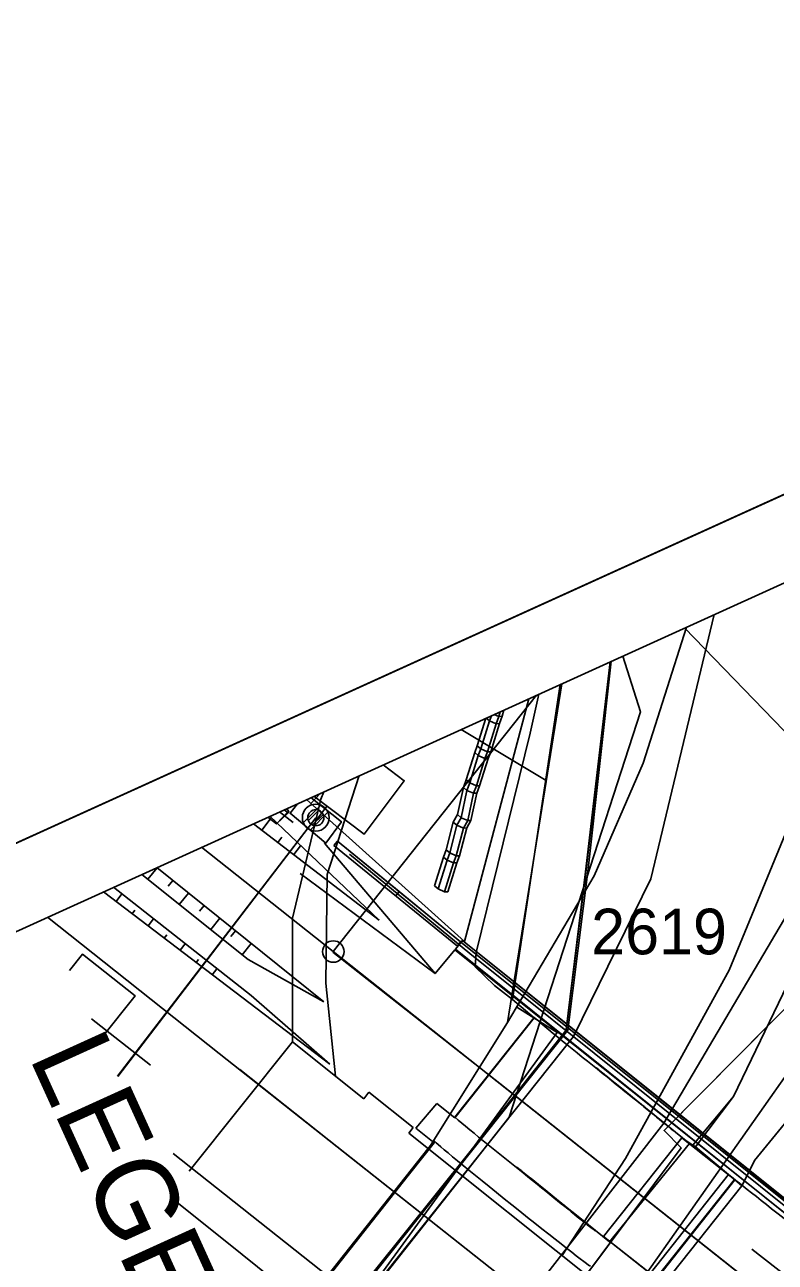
# Model space of a CAD drawing. Extents: x -735603 to -735159, y -1043062 to -1042557.
# Drawn here: x -735536.9 to -735508.95, y -1042665.87 to -1042619.77 of the extents above; entities that cross this region are included whole.
import ezdxf

# ---------------------------------------------------------------- set-up
doc = ezdxf.new("R2010")
doc.units = 0
for name, color, linetype in [('01_ramecek', 7, 'Continuous'), ('02_hranice parcel KN', 7, 'Continuous'), ('03_hranice dráhy', 7, 'Continuous'), ('05_vnitřní kresba', 7, 'Continuous'), ('095_LEGENDA', 7, 'Continuous'), ('CD_6kV', 7, 'Continuous'), ('CD_Telematika', 7, 'Continuous'), ('komunikace_chodníky', 7, 'Continuous'), ('mosty', 7, 'Continuous'), ('nn_ osvetl - ČD', 7, 'Continuous'), ('obvod stavby', 7, 'Continuous'), ('obvod_staveniste', 7, 'Continuous'), ('ploty_zdi_zábradlí_svodidla_vchody', 7, 'Continuous'), ('propustky', 7, 'Continuous'), ('rampy_patky_sokly', 7, 'Continuous'), ('SO_11-80-01_02_TV', 7, 'Continuous'), ('strom_komín_skála_pramen_močál', 7, 'Continuous'), ('teréní hrany a čáry', 7, 'Continuous'), ('Vrstva 1', 7, 'Continuous'), ('Vrstva 11', 7, 'Continuous'), ('Vrstva 12', 7, 'Continuous'), ('Vrstva 13', 7, 'Continuous'), ('Vrstva 17', 7, 'Continuous'), ('Vrstva 18', 7, 'Continuous'), ('Vrstva 4', 7, 'Continuous'), ('Vrstva 48', 7, 'Continuous'), ('Vrstva 49', 7, 'Continuous'), ('Vrstva 5', 7, 'Continuous'), ('Vrstva 7', 7, 'Continuous')]:
    doc.layers.add(name, color=color, linetype=linetype)

msp = doc.modelspace()

# ---------------------------------------------------------------- linework, layer by layer
at = {"layer": '01_ramecek'}
msp.add_line((-735602.799, -1042680.046), (-735332.394, -1042557.205), dxfattribs=at)
for points in [[(-735245.537, -1042748.401), (-735332.394, -1042557.205), (-735602.799, -1042680.046), (-735515.942, -1042871.242)], [(-735249.509, -1042746.911), (-735333.884, -1042561.178), (-735598.827, -1042681.537), (-735514.452, -1042867.27)]]:
    msp.add_lwpolyline(points, close=True, dxfattribs=at)
at = {"layer": '02_hranice parcel KN'}
for p, q in [((-735516.904, -1042644.32), (-735518.917, -1042656.943)), ((-735513.09, -1042660.96), (-735500.521, -1042648.267)), ((-735518.917, -1042656.943), (-735521.974, -1042661.816)), ((-735513.09, -1042660.96), (-735513.09, -1042660.96)), ((-735512.461, -1042661.611), (-735513.09, -1042660.96)), ((-735524.091, -1042677.193), (-735512.461, -1042661.611)), ((-735521.974, -1042661.816), (-735527.426, -1042668.733))]:
    msp.add_line(p, q, dxfattribs=at)
at = {"layer": '03_hranice dráhy'}
for points in [[(-735516.904, -1042644.32), (-735518.917, -1042656.943), (-735521.974, -1042661.816), (-735527.426, -1042668.733), (-735527.784, -1042669.063)], [(-735524.091, -1042677.193), (-735512.461, -1042661.611), (-735513.09, -1042660.96), (-735500.521, -1042648.267), (-735489.9, -1042656.38), (-735493.161, -1042657.849), (-735483.827, -1042665.226), (-735477.631, -1042665.199), (-735440.604, -1042695.204), (-735421.335, -1042710.908), (-735395.309, -1042732.033), (-735386.642, -1042739.64), (-735367.665, -1042760.814), (-735350.022, -1042783.766), (-735345.024, -1042786.048), (-735341.588, -1042788.741)]]:
    msp.add_lwpolyline(points, dxfattribs=at)
at = {"layer": '05_vnitřní kresba'}
for p, q in [((-735513.87, -1042647.28), (-735512.257, -1042642.209)), ((-735507.24, -1042646.65), (-735510.67, -1042654.99)), ((-735515.69, -1042651.47), (-735513.87, -1042647.28)), ((-735524.441, -1042647.744), (-735525.63, -1042651.42)), ((-735526.93, -1042653.05), (-735525.87, -1042648.62)), ((-735525.87, -1042648.62), (-735525.755, -1042648.341)), ((-735502.59, -1042650.43), (-735514.6, -1042667.5)), ((-735525.63, -1042651.42), (-735525.68, -1042655.47)), ((-735518.917, -1042656.943), (-735515.69, -1042651.47)), ((-735526.93, -1042657.66), (-735526.93, -1042653.05)), ((-735510.67, -1042654.99), (-735514.53, -1042662.01)), ((-735525.68, -1042655.47), (-735525.321, -1042658.943)), ((-735517.07, -1042657.31), (-735518.578, -1042656.368)), ((-735526.1, -1042669.7), (-735517.07, -1042657.31)), ((-735530.775, -1042662.48), (-735526.93, -1042657.66)), ((-735526.93, -1042657.66), (-735524.271, -1042659.781)), ((-735524.271, -1042659.781), (-735524.079, -1042659.541)), ((-735524.079, -1042659.541), (-735522.433, -1042660.854)), ((-735522.433, -1042660.854), (-735522.598, -1042661.061)), ((-735522.598, -1042661.061), (-735500.951, -1042678.331)), ((-735514.53, -1042662.01), (-735516.881, -1042665.622))]:
    msp.add_line(p, q, dxfattribs=at)
at = {"layer": 'CD_6kV'}
msp.add_lwpolyline([(-735371.534, -1042802.345), (-735396.434, -1042783.658), (-735432.138, -1042755.539), (-735468.875, -1042727.3), (-735473.985, -1042719.335), (-735497.239, -1042697.412), (-735502.875, -1042686.463), (-735529.314, -1042665.17), (-735531.344, -1042663.551)], dxfattribs=at)
at = {"layer": 'CD_Telematika'}
msp.add_line((-735509.263, -1042667.093), (-735525.409, -1042654.296), dxfattribs=at)
for points in [[(-735525.409, -1042654.296), (-735530.314, -1042650.412)], [(-735512.743, -1042671.484), (-735529.653, -1042658.093), (-735536.052, -1042653.019)], [(-735475.42, -1042693.902), (-735478.1, -1042691.779), (-735485.962, -1042685.541), (-735494.268, -1042678.969), (-735502.317, -1042672.596), (-735509.263, -1042667.093), (-735510.894, -1042665.801), (-735519.202, -1042659.215), (-735525.425, -1042654.322)], [(-735422.013, -1042743.373), (-735429.981, -1042737.066), (-735437.697, -1042730.953), (-735445.383, -1042724.866), (-735453.615, -1042718.34), (-735461.55, -1042712.049), (-735469.622, -1042705.653), (-735477.37, -1042699.512), (-735485.158, -1042693.34), (-735493.098, -1042687.047), (-735501.332, -1042680.524), (-735509.533, -1042674.027), (-735512.743, -1042671.484), (-735517.309, -1042667.866), (-735525.575, -1042661.32), (-735528.887, -1042658.692)], [(-735360.405, -1042797.289), (-735365.246, -1042793.45), (-735373.079, -1042787.24), (-735381.089, -1042780.893), (-735388.559, -1042774.975), (-735396.608, -1042768.597), (-735404.378, -1042762.439), (-735412.699, -1042755.841), (-735420.83, -1042749.397), (-735428.938, -1042742.976), (-735437.234, -1042736.405), (-735445.067, -1042730.203), (-735453.018, -1042723.906), (-735460.767, -1042717.765), (-735468.725, -1042711.459), (-735476.643, -1042705.186), (-735484.416, -1042699.028), (-735492.498, -1042692.627), (-735500.555, -1042686.242), (-735508.644, -1042679.831), (-735515.225, -1042674.616), (-735516.825, -1042673.349), (-735524.914, -1042666.938), (-735531.371, -1042661.825)]]:
    msp.add_lwpolyline(points, dxfattribs=at)
msp.add_circle((-735525.409, -1042654.296), 0.4, dxfattribs=at)
at = {"layer": 'komunikace_chodníky'}
for points in [[(-735527.848, -1042671.247), (-735526.071, -1042669.543), (-735516.46, -1042657.467), (-735513.586, -1042651.585), (-735511.227, -1042641.741)], [(-735525.703, -1042675.969), (-735524.134, -1042674.542), (-735522.081, -1042672.259), (-735513.099, -1042660.691), (-735507.555, -1042651.293), (-735499.234, -1042642.083), (-735497.448, -1042641.728), (-735495.789, -1042642.183)]]:
    msp.add_lwpolyline(points, dxfattribs=at)
at = {"layer": 'mosty'}
for p, q in [((-735517.931, -1042656.75), (-735520.881, -1042660.468)), ((-735510.512, -1042659.694), (-735511.918, -1042661.575)), ((-735521.55, -1042659.962), (-735522.334, -1042660.881)), ((-735521.55, -1042659.962), (-735520.884, -1042660.49)), ((-735522.334, -1042660.881), (-735521.653, -1042661.422)), ((-735512.435, -1042661.234), (-735515.342, -1042664.909)), ((-735510.474, -1042662.785), (-735512.435, -1042661.234)), ((-735527.179, -1042668.342), (-735521.653, -1042661.349)), ((-735521.653, -1042661.422), (-735521.653, -1042661.349)), ((-735515.128, -1042665.108), (-735512.15, -1042661.443)), ((-735510.687, -1042662.6), (-735513.594, -1042666.275)), ((-735513.381, -1042666.46), (-735510.474, -1042662.785)), ((-735510.453, -1042662.807), (-735513.36, -1042666.482)), ((-735510.201, -1042663.024), (-735513.108, -1042666.699)), ((-735513.36, -1042666.482), (-735515.342, -1042664.909)), ((-735513.381, -1042666.46), (-735515.342, -1042664.909)), ((-735515.342, -1042664.909), (-735515.128, -1042665.108))]:
    msp.add_line(p, q, dxfattribs=at)
for points in [[(-735516.966, -1042644.349), (-735518.731, -1042656.083), (-735517.934, -1042656.772), (-735520.884, -1042660.49)], [(-735517.757, -1042644.708), (-735518.078, -1042646.159), (-735520.094, -1042654.33), (-735520.13, -1042654.872)], [(-735520.13, -1042654.872), (-735519.41, -1042655.556), (-735518.731, -1042656.083)], [(-735517.934, -1042656.772), (-735517.931, -1042656.75)], [(-735520.884, -1042660.49), (-735520.881, -1042660.468)], [(-735512.15, -1042661.443), (-735512.435, -1042661.234), (-735512.018, -1042661.506), (-735511.918, -1042661.575), (-735510.453, -1042662.807)], [(-735521.653, -1042661.422), (-735527.161, -1042668.357)], [(-735510.172, -1042662.992), (-735510.201, -1042663.024), (-735510.453, -1042662.807), (-735510.474, -1042662.785), (-735510.687, -1042662.6)]]:
    msp.add_lwpolyline(points, dxfattribs=at)
msp.add_ellipse((-735518.739, -1042663.684), major_axis=(-2.915, 2.338), ratio=0.01386, start_param=0.03466, end_param=3.118179, dxfattribs=at)
for points in [[(-735517.931, -1042656.75), (-735517.315, -1042657.285), (-735514.993, -1042659.14), (-735512.834, -1042660.901), (-735512.15, -1042661.443), (-735517.931, -1042656.75), (-735512.15, -1042661.443)], [(-735520.881, -1042660.468), (-735520.265, -1042661.003), (-735517.943, -1042662.858), (-735515.784, -1042664.619), (-735515.128, -1042665.108), (-735520.881, -1042660.468), (-735515.128, -1042665.108)], [(-735510.687, -1042662.6), (-735510.36, -1042662.873), (-735507.897, -1042664.815), (-735505.351, -1042666.837), (-735504.929, -1042667.171), (-735510.687, -1042662.6), (-735504.929, -1042667.171)]]:
    msp.add_open_spline(points, degree=3, dxfattribs=at)
at = {"layer": 'nn_ osvetl - ČD'}
msp.add_lwpolyline([(-735514.63, -1042643.287), (-735513.971, -1042645.361), (-735518.865, -1042660.469), (-735527.668, -1042671.643)], dxfattribs=at)
at = {"layer": 'obvod stavby'}
msp.add_line((-735520.644, -1042646.019), (-735517.479, -1042647.928), dxfattribs=at)
for points in [[(-735517.479, -1042647.928), (-735516.904, -1042644.32)], [(-735421.335, -1042710.908), (-735452.068, -1042685.91), (-735452.98, -1042683.675), (-735457.204, -1042677.405), (-735460.757, -1042678.873), (-735461.466, -1042678.3), (-735477.631, -1042665.199), (-735479.332, -1042663.846), (-735472.373, -1042659.113), (-735477.997, -1042650.844), (-735487.919, -1042657.593), (-735489.9, -1042656.38), (-735500.521, -1042648.267), (-735513.09, -1042660.96), (-735512.461, -1042661.611), (-735524.747, -1042678.072)]]:
    msp.add_lwpolyline(points, dxfattribs=at)
at = {"layer": 'obvod_staveniste'}
msp.add_line((-735512.328, -1042642.242), (-735503.555, -1042651.331), dxfattribs=at)
at = {"layer": 'ploty_zdi_zábradlí_svodidla_vchody'}
msp.add_lwpolyline([(-735515.1, -1042643.501), (-735516.02, -1042651.321), (-735516.751, -1042657.3), (-735526.334, -1042669.259), (-735527.97, -1042670.771)], dxfattribs=at)
at = {"layer": 'propustky'}
msp.add_line((-735510.512, -1042659.694), (-735512.018, -1042661.506), dxfattribs=at)
at = {"layer": 'rampy_patky_sokly'}
for points in [[(-735528.021, -1042670.866), (-735526.349, -1042669.369), (-735516.731, -1042657.23), (-735515.998, -1042651.243), (-735515.086, -1042643.494)], [(-735515.062, -1042643.484), (-735515.923, -1042651.213), (-735516.677, -1042657.228), (-735526.371, -1042669.402), (-735528.015, -1042670.878)]]:
    msp.add_lwpolyline(points, dxfattribs=at)
at = {"layer": 'SO_11-80-01_02_TV'}
for p, q in [((-735526.335, -1042649.42), (-735525.947, -1042649.033)), ((-735526.179, -1042649.582), (-735525.786, -1042649.189)), ((-735526.058, -1042649.31), (-735533.436, -1042658.947))]:
    msp.add_line(p, q, dxfattribs=at)
msp.add_lwpolyline([(-735526.241, -1042648.562), (-735525.108, -1042649.463), (-735525.686, -1042650.253), (-735527.016, -1042649.143), (-735526.741, -1042648.789)], dxfattribs=at)
msp.add_circle((-735526.058, -1042649.31), 0.3, dxfattribs=at)
at = {"layer": 'strom_komín_skála_pramen_močál'}
msp.add_lwpolyline([(-735510.172, -1042662.992), (-735509.725, -1042662.084), (-735503.813, -1042654.859), (-735498.11, -1042649.926), (-735490.483, -1042645.367), (-735480.385, -1042642.706), (-735472.541, -1042642.407), (-735463.647, -1042643.532), (-735461.652, -1042643.46), (-735458.133, -1042644.484), (-735457.173, -1042644.864), (-735456.449, -1042645.282), (-735454.933, -1042645.72), (-735453.782, -1042646.119), (-735453.351, -1042646.767), (-735448.493, -1042649.698), (-735445.79, -1042649.249), (-735441.648, -1042651.713), (-735436.193, -1042653.417), (-735435.455, -1042652.45), (-735418.005, -1042659.075), (-735400.775, -1042666.18)], dxfattribs=at)
at = {"layer": 'teréní hrany a čáry'}
msp.add_lwpolyline([(-735497.448, -1042641.728), (-735502.107, -1042648.331), (-735508.33, -1042655.187), (-735510.512, -1042659.694)], dxfattribs=at)
at = {"layer": 'Vrstva 1'}
for p, q in [((-735525.409, -1042654.296), (-735517.84, -1042644.745)), ((-735509.263, -1042667.093), (-735525.409, -1042654.296)), ((-735507.466, -1042667.241), (-735509.818, -1042665.378))]:
    msp.add_line(p, q, dxfattribs=at)
for points in [[(-735525.409, -1042654.296), (-735530.314, -1042650.412)], [(-735512.743, -1042671.484), (-735529.653, -1042658.093), (-735536.052, -1042653.019)], [(-735532.408, -1042661.003), (-735532.554, -1042660.887)], [(-735360.405, -1042797.289), (-735365.246, -1042793.45), (-735373.079, -1042787.24), (-735381.089, -1042780.893), (-735388.559, -1042774.975), (-735396.608, -1042768.597), (-735404.378, -1042762.439), (-735412.699, -1042755.841), (-735420.83, -1042749.397), (-735428.938, -1042742.976), (-735437.234, -1042736.405), (-735445.067, -1042730.203), (-735453.018, -1042723.906), (-735460.767, -1042717.765), (-735468.725, -1042711.459), (-735476.643, -1042705.186), (-735484.416, -1042699.028), (-735492.498, -1042692.627), (-735500.555, -1042686.242), (-735508.644, -1042679.831), (-735515.225, -1042674.616), (-735516.825, -1042673.349), (-735524.914, -1042666.938), (-735531.371, -1042661.825)]]:
    msp.add_lwpolyline(points, dxfattribs=at)
msp.add_circle((-735525.409, -1042654.296), 0.4, dxfattribs=at)
at = {"layer": 'Vrstva 11'}
for p, q in [((-735526.522, -1042649.493), (-735525.875, -1042648.848)), ((-735526.262, -1042649.763), (-735525.607, -1042649.108)), ((-735526.06, -1042649.31), (-735533.438, -1042658.943))]:
    msp.add_line(p, q, dxfattribs=at)
msp.add_circle((-735526.06, -1042649.31), 0.5, dxfattribs=at)
at = {"layer": 'Vrstva 12'}
msp.add_lwpolyline([(-735526.241, -1042648.562), (-735525.108, -1042649.463), (-735525.686, -1042650.253), (-735527.016, -1042649.143), (-735526.741, -1042648.789)], dxfattribs=at)
at = {"layer": 'Vrstva 13'}
for p, q in [((-735519.594, -1042645.701), (-735519.523, -1042645.51)), ((-735519.245, -1042645.534), (-735519.412, -1042645.46)), ((-735519.245, -1042645.534), (-735519.348, -1042645.81)), ((-735519.196, -1042645.361), (-735519.245, -1042645.534)), ((-735519.122, -1042645.531), (-735519.245, -1042645.534)), ((-735519.225, -1042645.807), (-735519.122, -1042645.531)), ((-735519.122, -1042645.531), (-735519.056, -1042645.298)), ((-735519.73, -1042645.604), (-735520.047, -1042646.637)), ((-735519.916, -1042646.75), (-735519.594, -1042645.701)), ((-735519.594, -1042645.701), (-735519.715, -1042645.597)), ((-735519.348, -1042645.81), (-735519.67, -1042646.859)), ((-735519.348, -1042645.81), (-735519.594, -1042645.701)), ((-735519.547, -1042646.856), (-735519.225, -1042645.807)), ((-735519.225, -1042645.807), (-735519.348, -1042645.81)), ((-735520.142, -1042646.882), (-735520.458, -1042647.904)), ((-735520.047, -1042646.637), (-735520.142, -1042646.882)), ((-735520.011, -1042646.995), (-735520.142, -1042646.882)), ((-735519.916, -1042646.75), (-735520.047, -1042646.637)), ((-735520.011, -1042646.995), (-735519.916, -1042646.75)), ((-735519.67, -1042646.859), (-735519.916, -1042646.75)), ((-735519.67, -1042646.859), (-735519.765, -1042647.104)), ((-735519.547, -1042646.856), (-735519.67, -1042646.859)), ((-735519.642, -1042647.101), (-735519.547, -1042646.856)), ((-735520.327, -1042648.017), (-735520.011, -1042646.995)), ((-735519.765, -1042647.104), (-735520.081, -1042648.126)), ((-735519.765, -1042647.104), (-735520.011, -1042646.995)), ((-735519.958, -1042648.123), (-735519.642, -1042647.101)), ((-735519.642, -1042647.101), (-735519.765, -1042647.104)), ((-735520.563, -1042648.18), (-735520.781, -1042649.196)), ((-735520.65, -1042649.309), (-735520.432, -1042648.293)), ((-735520.458, -1042647.904), (-735520.563, -1042648.18)), ((-735520.432, -1042648.293), (-735520.563, -1042648.18)), ((-735520.327, -1042648.017), (-735520.458, -1042647.904)), ((-735520.432, -1042648.293), (-735520.327, -1042648.017)), ((-735520.186, -1042648.402), (-735520.432, -1042648.293)), ((-735520.081, -1042648.126), (-735520.327, -1042648.017)), ((-735520.081, -1042648.126), (-735520.186, -1042648.402)), ((-735519.958, -1042648.123), (-735520.081, -1042648.126)), ((-735520.063, -1042648.399), (-735519.958, -1042648.123)), ((-735520.186, -1042648.402), (-735520.404, -1042649.418)), ((-735520.281, -1042649.415), (-735520.063, -1042648.399)), ((-735520.063, -1042648.399), (-735520.186, -1042648.402)), ((-735527.065, -1042649.052), (-735527.526, -1042649.543)), ((-735527.065, -1042649.052), (-735527.158, -1042648.978)), ((-735520.781, -1042649.196), (-735520.941, -1042649.473)), ((-735520.65, -1042649.309), (-735520.781, -1042649.196)), ((-735520.941, -1042649.473), (-735521.204, -1042650.506)), ((-735521.073, -1042650.619), (-735520.81, -1042649.586)), ((-735520.81, -1042649.586), (-735520.941, -1042649.473)), ((-735520.564, -1042649.695), (-735520.827, -1042650.728)), ((-735520.81, -1042649.586), (-735520.65, -1042649.309)), ((-735520.564, -1042649.695), (-735520.81, -1042649.586)), ((-735520.704, -1042650.725), (-735520.441, -1042649.692)), ((-735520.404, -1042649.418), (-735520.65, -1042649.309)), ((-735520.404, -1042649.418), (-735520.564, -1042649.695)), ((-735520.441, -1042649.692), (-735520.564, -1042649.695)), ((-735520.441, -1042649.692), (-735520.281, -1042649.415)), ((-735520.281, -1042649.415), (-735520.404, -1042649.418)), ((-735521.204, -1042650.506), (-735521.305, -1042650.775)), ((-735521.073, -1042650.619), (-735521.204, -1042650.506)), ((-735521.174, -1042650.888), (-735521.073, -1042650.619)), ((-735520.827, -1042650.728), (-735521.073, -1042650.619)), ((-735521.305, -1042650.775), (-735521.639, -1042651.853)), ((-735521.508, -1042651.966), (-735521.174, -1042650.888)), ((-735521.174, -1042650.888), (-735521.305, -1042650.775)), ((-735520.928, -1042650.997), (-735521.262, -1042652.075)), ((-735520.928, -1042650.997), (-735521.174, -1042650.888)), ((-735521.139, -1042652.072), (-735520.805, -1042650.994)), ((-735520.827, -1042650.728), (-735520.928, -1042650.997)), ((-735520.805, -1042650.994), (-735520.928, -1042650.997)), ((-735520.704, -1042650.725), (-735520.827, -1042650.728)), ((-735520.805, -1042650.994), (-735520.704, -1042650.725)), ((-735521.508, -1042651.966), (-735521.639, -1042651.853)), ((-735521.262, -1042652.075), (-735521.508, -1042651.966)), ((-735521.139, -1042652.072), (-735521.262, -1042652.075))]:
    msp.add_line(p, q, dxfattribs=at)
for points in [[(-735527.847, -1042649.291), (-735527.526, -1042649.543), (-735527.089, -1042649.129)], [(-735527.065, -1042649.052), (-735527.089, -1042649.129), (-735527.235, -1042649.013)]]:
    msp.add_lwpolyline(points, dxfattribs=at)
at = {"layer": 'Vrstva 17'}
for p, q in [((-735526.903, -1042649.495), (-735527.411, -1042649.094)), ((-735520.329, -1042654.375), (-735524.803, -1042650.668)), ((-735507.941, -1042664.307), (-735520.329, -1042654.375))]:
    msp.add_line(p, q, dxfattribs=at)
at = {"layer": 'Vrstva 18'}
for p, q in [((-735518.131, -1042644.878), (-735520.525, -1042653.925)), ((-735525.252, -1042650.179), (-735525.384, -1042650.347)), ((-735525.252, -1042650.179), (-735525.384, -1042650.347)), ((-735525.384, -1042650.347), (-735520.789, -1042654.093)), ((-735520.666, -1042653.939), (-735525.252, -1042650.179)), ((-735525.252, -1042650.179), (-735525.252, -1042650.179)), ((-735525.252, -1042650.179), (-735522.955, -1042652.062)), ((-735522.954, -1042652.063), (-735523.085, -1042652.221)), ((-735522.955, -1042652.062), (-735522.954, -1042652.063)), ((-735522.955, -1042652.062), (-735520.666, -1042653.939)), ((-735520.603, -1042653.882), (-735520.859, -1042654.212)), ((-735520.859, -1042654.212), (-735503.332, -1042668.263)), ((-735520.789, -1042654.093), (-735520.666, -1042653.939)), ((-735520.666, -1042653.939), (-735520.666, -1042653.939)), ((-735520.654, -1042653.948), (-735520.603, -1042653.882)), ((-735520.654, -1042653.948), (-735520.654, -1042653.948)), ((-735494.314, -1042675.049), (-735520.654, -1042653.948)), ((-735520.654, -1042653.948), (-735494.314, -1042675.049)), ((-735520.603, -1042653.882), (-735507.476, -1042664.429)), ((-735520.603, -1042653.882), (-735520.603, -1042653.882)), ((-735520.603, -1042653.882), (-735494.259, -1042674.981))]:
    msp.add_line(p, q, dxfattribs=at)
at = {"layer": 'Vrstva 4'}
for points in [[(-735523.705, -1042653.125), (-735528.378, -1042649.533)], [(-735523.705, -1042653.125), (-735527.776, -1042649.259)], [(-735489.387, -1042681.048), (-735495.248, -1042676.294), (-735494.501, -1042675.295), (-735520.884, -1042654.237), (-735521.62, -1042655.116), (-735525.735, -1042650.262)], [(-735525.761, -1042656.169), (-735528.583, -1042654.595), (-735532.534, -1042651.421)], [(-735531.979, -1042651.169), (-735525.761, -1042656.169)], [(-735521.62, -1042655.116), (-735526.646, -1042651.388)], [(-735533.595, -1042651.903), (-735528.466, -1042655.94), (-735525.534, -1042658.498)], [(-735525.534, -1042658.498), (-735533.966, -1042652.071)], [(-735532.214, -1042658.525), (-735534.41, -1042656.801)]]:
    msp.add_lwpolyline(points, dxfattribs=at)
at = {"layer": 'Vrstva 48'}
for p, q in [((-735526.24, -1042648.786), (-735525.899, -1042648.407)), ((-735528.067, -1042649.772), (-735527.716, -1042649.316)), ((-735527.472, -1042650.229), (-735527.321, -1042650.032)), ((-735526.878, -1042650.686), (-735526.623, -1042650.354)), ((-735531.97, -1042651.176), (-735532.311, -1042651.6)), ((-735531.386, -1042651.646), (-735531.556, -1042651.858)), ((-735533.493, -1042652.432), (-735533.279, -1042652.151)), ((-735530.801, -1042652.116), (-735531.141, -1042652.54)), ((-735532.897, -1042652.887), (-735532.793, -1042652.751)), ((-735530.217, -1042652.586), (-735530.387, -1042652.798)), ((-735532.3, -1042653.341), (-735532.1, -1042653.079)), ((-735529.632, -1042653.056), (-735529.972, -1042653.479)), ((-735531.703, -1042653.796), (-735531.607, -1042653.67)), ((-735529.048, -1042653.526), (-735529.218, -1042653.737)), ((-735531.107, -1042654.251), (-735530.921, -1042654.007)), ((-735528.463, -1042653.996), (-735528.803, -1042654.418)), ((-735530.51, -1042654.705), (-735530.421, -1042654.588)), ((-735529.914, -1042655.16), (-735529.743, -1042654.935))]:
    msp.add_line(p, q, dxfattribs=at)
at = {"layer": 'Vrstva 49'}
msp.add_lwpolyline([(-735520.525, -1042653.925), (-735526.406, -1042648.637)], dxfattribs=at)
at = {"layer": 'Vrstva 5'}
msp.add_lwpolyline([(-735534.069, -1042657.553), (-735532.788, -1042655.946), (-735534.743, -1042654.388), (-735535.23, -1042654.998)], dxfattribs=at)
at = {"layer": 'Vrstva 7'}
msp.add_line((-735526.026, -1042649.374), (-735525.653, -1042648.875), dxfattribs=at)
msp.add_lwpolyline([(-735523.556, -1042647.342), (-735522.768, -1042647.932), (-735524.255, -1042649.92), (-735526.136, -1042648.514)], dxfattribs=at)

# ---------------------------------------------------------------- texts
at = {"layer": '02_hranice parcel KN'}
msp.add_text('2619', height=1.7, dxfattribs=at).set_placement((-735515.808, -1042654.4))
at = {"layer": '095_LEGENDA'}
msp.add_text('LEGENDA:', height=3, rotation=294.4315, dxfattribs=at).set_placement((-735536.756, -1042658.212))

doc.saveas('drawing.dxf')
